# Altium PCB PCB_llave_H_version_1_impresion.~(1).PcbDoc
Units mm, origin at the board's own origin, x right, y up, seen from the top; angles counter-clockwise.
Board outline 85.85 x 71.63 mm, 2 copper layers (Top Layer, Bottom Layer); 58 components, 33 nets, 172 pads, 5 vias.
Unrouted connection lines stored in the file: 5.
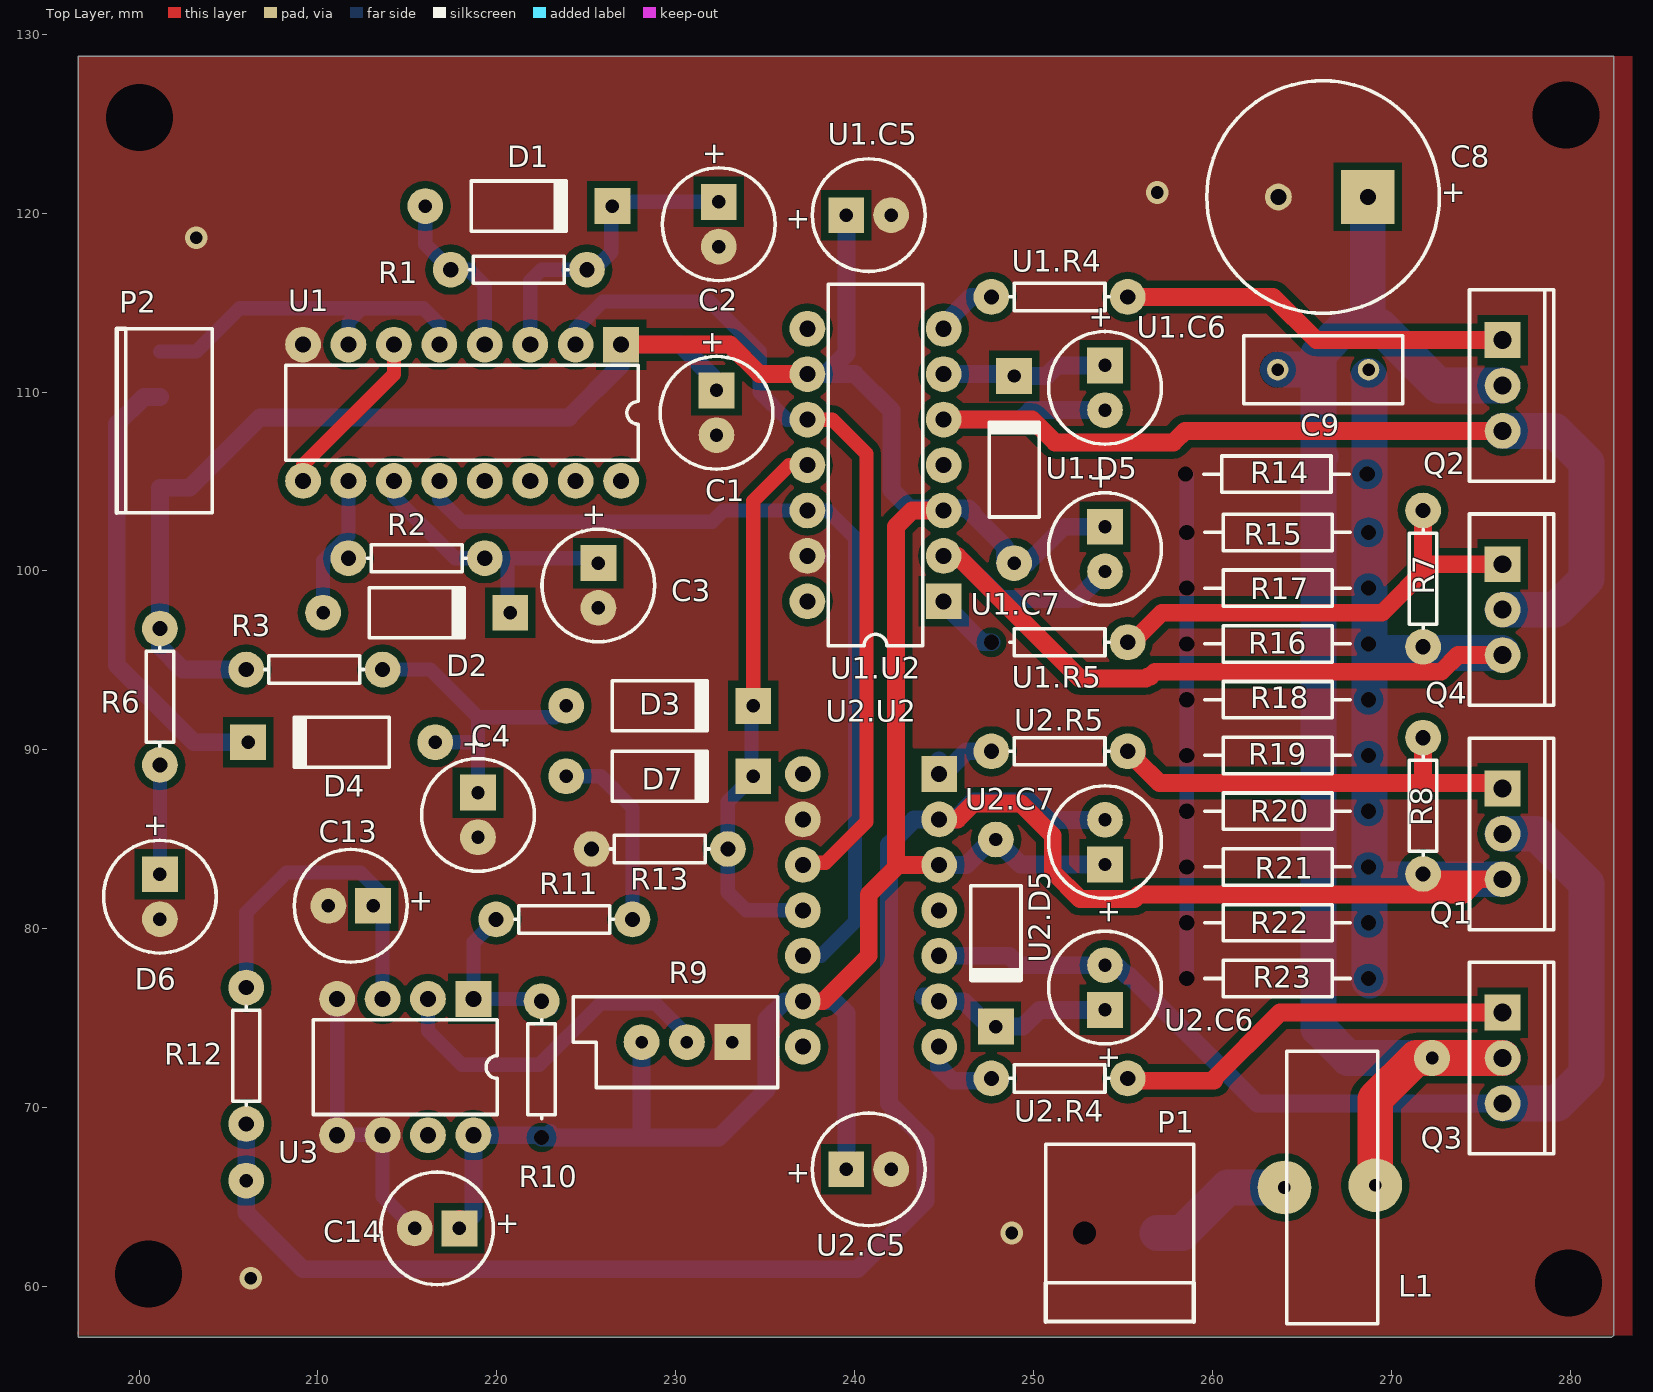
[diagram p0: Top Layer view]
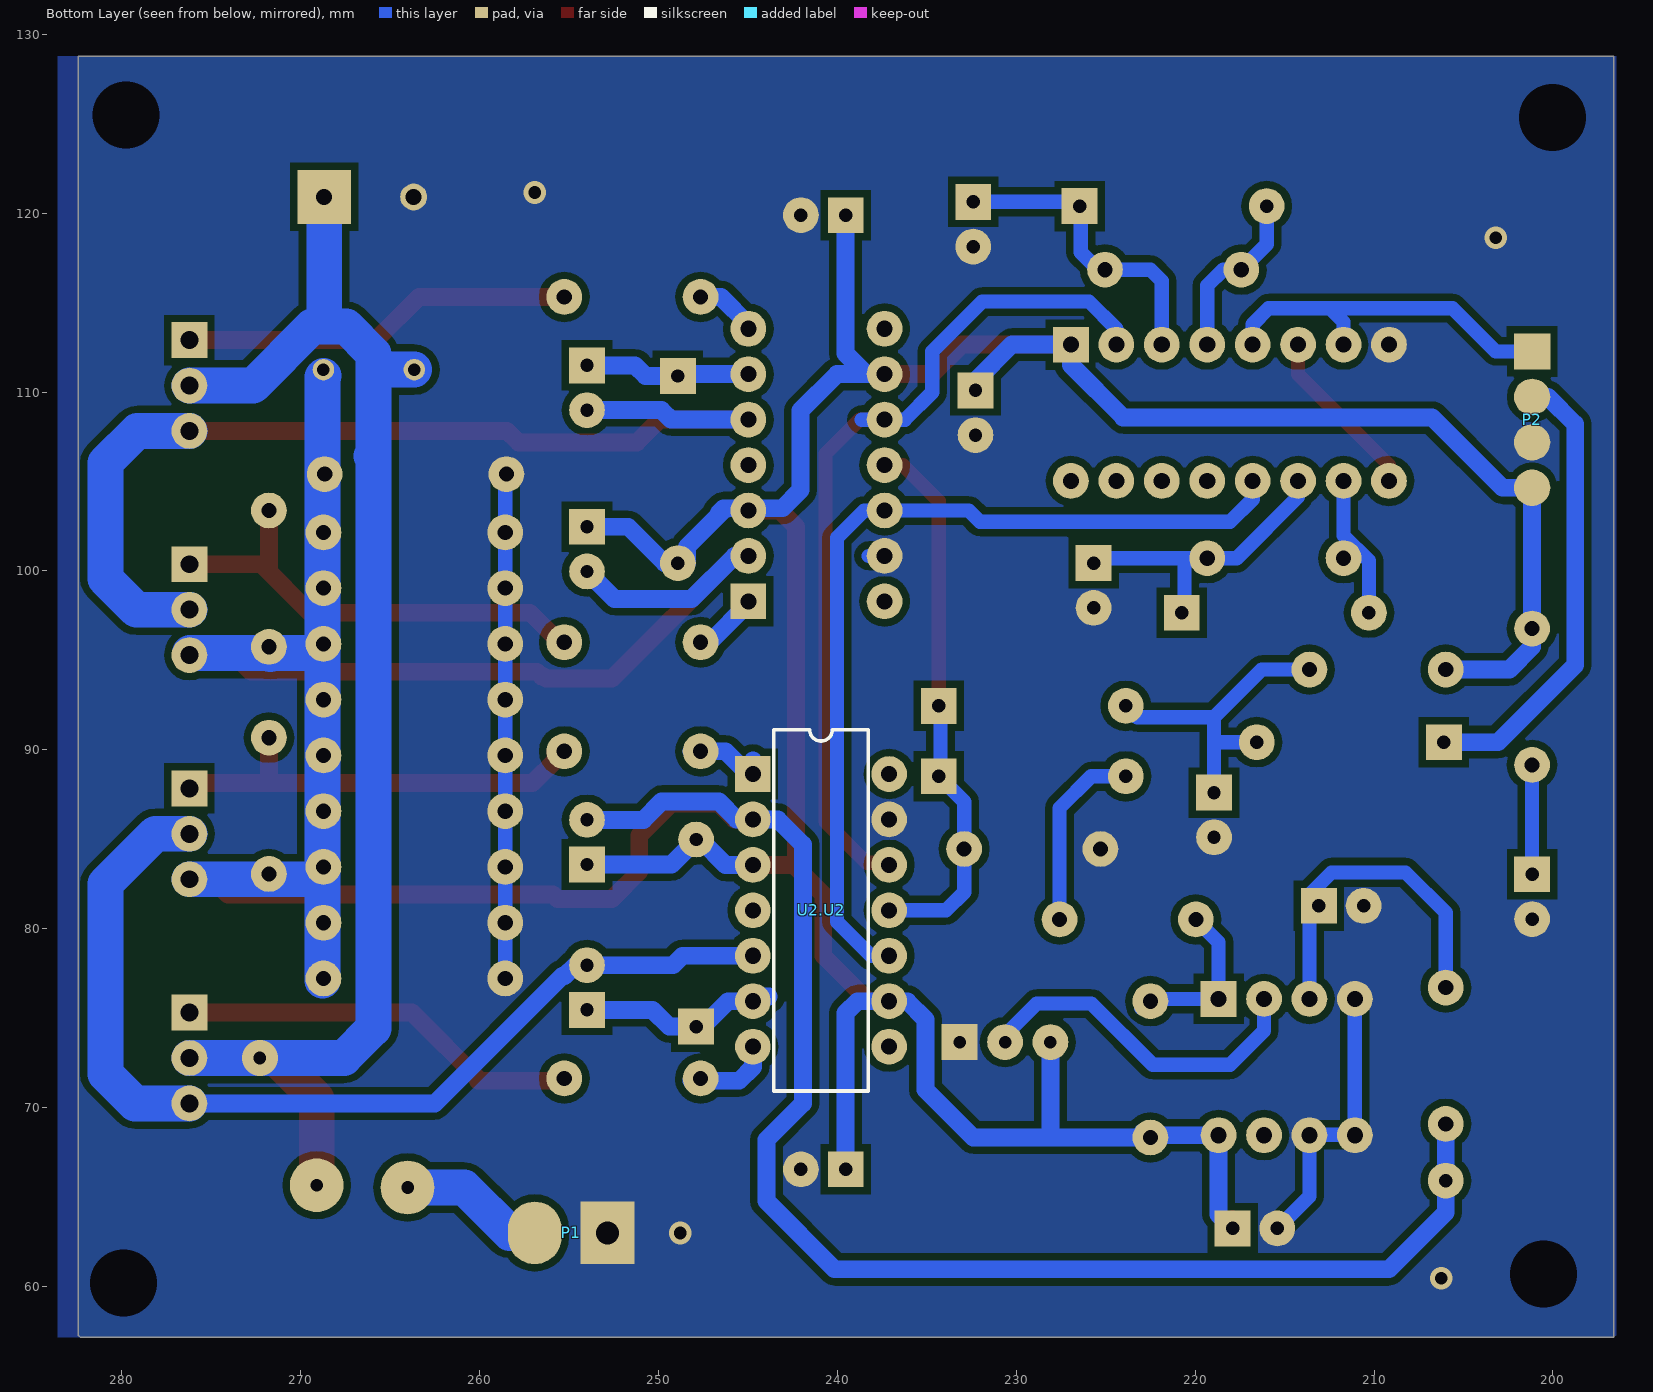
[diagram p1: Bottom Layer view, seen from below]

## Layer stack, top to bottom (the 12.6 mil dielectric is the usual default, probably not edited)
Top Layer: signal copper 0.0356
Dielectric: dielectric 0.32, FR-4, Dk 4.8
Bottom Layer: signal copper 0.0356

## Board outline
196.596,128.778 282.448,128.778 282.448,57.277 282.321,57.15 196.596,57.15

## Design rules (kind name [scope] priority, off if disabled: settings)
Clearance [All] p1: gap=0.4
ComponentClearance [All] p1: gap=0.254 collisioncheckmode=2 verticalgap=0.254
PlaneConnect [All] p1: planeconnectstyle=Direct reliefexpansion=0.508 reliefentries=4 reliefconductorwidth=0.254 reliefairgap=0.254
PolygonConnect [All] p1: connectstyle=Direct reliefconductorwidth=0.254 reliefentries=4 polygonreliefangle="90 Angle"
RoomDefinition U2 [InComponentClass('U2')] p1: confinementstyle=ConfineIn formatcopy=TRUE lockcomponents=FALSE outline 276.86,69.977 229.235,69.977 229.235,101.854 276.86,101.854
RoomDefinition U1 [InComponentClass('U1')] p2: confinementstyle=ConfineIn formatcopy=TRUE lockcomponents=FALSE outline 271.272,125.984 230.759,125.984 230.759,94.361 271.272,94.361
RoomDefinition U_Puente_H [InComponentClass('U_Puente_H')] p3: confinementstyle=ConfineIn formatcopy=TRUE lockcomponents=FALSE outline 282.448,127.635 282.448,57.277 247.65,57.277 247.65,127.635
RoomDefinition U_INITShutdown [InComponentClass('U_INITShutdown')] p4: confinementstyle=ConfineIn formatcopy=TRUE lockcomponents=FALSE outline 198.501,98.425 198.501,82.677 236.347,82.677 236.347,98.425
RoomDefinition U_Shutdown [InComponentClass('U_Shutdown')] p5: confinementstyle=ConfineOut formatcopy=TRUE lockcomponents=FALSE outline 201.041,96.266 202.438,96.266 202.438,92.964 201.041,92.964
RoomDefinition Llave_H_esquema [InComponentClass('Llave_H_esquema')] p6: confinementstyle=ConfineIn formatcopy=TRUE lockcomponents=FALSE outline 196.596,57.277 282.448,57.277 282.448,128.778 196.596,128.778
RoomDefinition U_4049 [InComponentClass('U_4049')] p7: confinementstyle=ConfineIn formatcopy=TRUE lockcomponents=FALSE outline 206.375,93.853 240.411,93.853 240.411,124.333 206.375,124.333
RoutingVias [All] p1: holewidth=0.711 width=1.27 viastyle="Through Hole" minholewidth=0.711 minwidth=1.27 maxholewidth=0.711 maxwidth=1.27
SolderMaskExpansion [All] p1: expansion=0.102
TestPointUsage [All] p1: valid=0 allowmultiple=FALSE
Testpoint [All] p1: side=15 testpointundercomponent=TRUE minsize=1.016 maxsize=2.54 preferedsize=1.524 minholesize=0 maxholesize=1.016 preferedholesize=0.813 testpointgrid=0.025 style=1023 order=0-112345678
Width [All] p1: maxlimit=3 minlimit=0.8 preferedwidth=1
17 further rules are at their usual default settings.

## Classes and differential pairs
component class U2: D5 U2.C5 U2.C6 U2.C7 U2.D5 U2.R4 U2.R5 U2.U2 U_2.D5 U_2_C5 U_2_C6 U_2_C7 U_2_R4 U_2_R5 U_2_U2
component class U1: U1.C5 U1.C6 U1.C7 U1.D5 U1.R4 U1.R5 U1.U2 U_1_C5 U_1_C6 U_1_C7 U_1_D5 U_1_R4 U_1_R5 U_1_U2
component class U_INITShutdown: C4 D3 D4 R3
channel class IR2110: U1 U2
component class U_Shutdown: C13 C14 D7 R9 R10 R11 R12 R13 R14 R15 R16 R17 R18 R19 R20 R21 R22 R23 U3
component class U_Puente_H: C8 C9 L1 Q1 Q2 Q3 Q4 R7 R8
component class U_4049: C1 C2 C3 D1 D2 R1 R2 U1
component class Llave_H_esquema: D6 P1 P2 R6

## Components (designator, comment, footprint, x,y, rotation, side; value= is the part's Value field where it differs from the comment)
C1 "Cap Pol1 0.1u" CAPPR2.5-6.3X5 232.283,108.839 r270 top
C2 "Cap Pol1" CAPPR2.5-6.3X5 232.41,119.38 r270 top
C3 "Cap Pol1" CAPPR2.5-6.3X5 225.679,99.187 r270 top
C4 "Cap Pol1 4.7u" CAPPR2.5-6.3X5 218.948,86.36 r270 top
C8 "Cap Pol1" CAPPR5-13X16 266.192,120.904 r180 top
C9 "Cap" RAD-0.2 266.192,111.252 r180 top
C13 "Cap Pol1 4.7u" CAPPR2.5-6.3X5 211.836,81.28 r180 top
C14 "Cap Pol1 0.1u" CAPPR2.5-6.3X5 216.662,63.246 r180 top
D1 "Diode1" DO-204AL 221.234,120.396 r0 top
D2 "Diode1" DO-204AL 215.519,97.663 r0 top
D3 "Diode1" DO-204AL 229.108,92.456 r0 top
D4 "Diode1" DO-204AL 211.328,90.424 r180 top
D6 "LED0" CAPPR2.5-6.3X5 201.168,81.788 r270 top
D7 "Diode1" DO-204AL 229.108,88.519 r0 top
L1 "Inductor" bobina_Choque 264.16,68.072 r270 top
P1 "Header 2" pwheader1x2 255.016,62.992 r0 top
P2 "Header 4" HDR1X5 193.548,104.648 r270 top
Q1 "IRF3205" TO-220AB 276.225,72.771 r270 top
Q2 "IRF3205" TO-220AB 276.225,110.363 r270 top
Q3 "IRF3205" TO-220AB 276.225,85.302 r270 top
Q4 "IRF3205" TO-220AB 276.225,97.832 r270 top
R1 "18k" AXIAL-0.3#1 221.234,116.84 r180 top
R2 "18k" AXIAL-0.3#1 215.519,100.711 r0 top
R3 "4.7k" AXIAL-0.3#1 209.804,94.488 r180 top
R6 "1.2k" AXIAL-0.3#1 201.168,92.964 r90 top
R7 "6.8" AXIAL-0.3#1 271.78,99.568 r90 top
R8 "6.8" AXIAL-0.3#2 271.78,86.868 r90 top
R9 "RPot" VR5 230.632,73.66 r180 top
R10 "3.3k" AXIAL-0.3#3 222.504,72.136 r270 top
R11 "470" AXIAL-0.3#1 223.774,80.518 r0 top
R12 "6.8" AXIAL-0.3#1 205.994,72.898 r90 top locked
R13 "10k" AXIAL-0.3#1 229.108,84.455 r0 top
R14 "Res2" AXIAL-0.4#1 263.585,105.41 r0 top
R15 "Res2" AXIAL-0.4#1 263.652,102.154 r0 top
R16 "Res2" AXIAL-0.4#1 263.652,99.037 r0 top
R17 "Res2" AXIAL-0.4#1 263.652,95.919 r0 top
R18 "Res2" AXIAL-0.4#1 263.652,92.802 r0 top
R19 "Res2" AXIAL-0.4#1 263.652,89.685 r0 top
R20 "Res2" AXIAL-0.4#2 263.652,86.568 r0 top
R21 "Res2" AXIAL-0.4#2 263.652,83.45 r0 top
R22 "Res2" AXIAL-0.4#2 263.652,80.333 r0 top
R23 "Res2" AXIAL-0.4#2 263.652,77.216 r0 top
U1 "MC54HC4049J" 620-09 218.059,108.839 r180 top
U1.C5 "Cap Pol1 4.7u" CAPPR2.5-6.3X5 240.792,119.888 r0 top (schematic designator C5)
U1.C6 "Cap Pol1" CAPPR2.5-6.3X5 254,110.236 r270 top (schematic designator C6)
U1.C7 "Cap Pol1" CAPPR2.5-6.3X5 254,101.219 r270 top (schematic designator C7)
U1.D5 "Diode" DO-204AL 248.92,105.664 r90 top (schematic designator D5)
U1.R4 "10" AXIAL-0.3#1 251.46,115.316 r0 top (schematic designator R4)
U1.R5 "10" AXIAL-0.3#4 251.46,96.012 r0 top (schematic designator R5)
U1.U2 "IR2110" PDIP14 241.173,105.918 r90 top (schematic designator U2)
U2.C5 "Cap Pol1 4.7u" CAPPR2.5-6.3X5 240.792,66.548 r0 top (schematic designator C5)
U2.C6 "Cap Pol1" CAPPR2.5-6.3X5 254,76.708 r90 top (schematic designator C6)
U2.C7 "Cap Pol1" CAPPR2.5-6.3X5 254,84.836 r90 top (schematic designator C7)
U2.D5 "Diode" DO-204AL 247.904,79.756 r270 top (schematic designator D5)
U2.R4 "10" AXIAL-0.3#1 251.46,71.628 r0 top (schematic designator R4)
U2.R5 "10" AXIAL-0.3#1 251.46,89.916 r0 top (schematic designator R5)
U2.U2 "IR2110" PDIP14 240.919,81.026 r270 bottom (schematic designator U2)
U3 "LM393N" 626-05 214.884,72.263 r180 top

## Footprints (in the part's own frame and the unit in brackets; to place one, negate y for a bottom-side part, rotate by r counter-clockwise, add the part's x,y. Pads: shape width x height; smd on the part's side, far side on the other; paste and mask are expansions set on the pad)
620-09 [mm] "DIP; 16 Leads; Row Spacing 7.62 mm; Pitch 2.54 mm"
  rect 2x2 hole 0.9: 1(-8.89,-3.81)
  round 2 hole 0.9: 2(-6.35,-3.81) 3(-3.81,-3.81) 4(-1.27,-3.81) 5(1.27,-3.81) 6(3.81,-3.81) 7(6.35,-3.81) 8(8.89,-3.81) 9(8.89,3.81) 10(6.35,3.81) 11(3.81,3.81) 12(1.27,3.81) 13(-1.27,3.81) 14(-3.81,3.81) 15(-6.35,3.81) 16(-8.89,3.81)
  silkscreen extent -9.85,-2.65 9.85,2.65
626-05 [mm] "DIP; 8 Leads; Row Spacing 7.62 mm; Pitch 2.54 mm"
  rect 2x2 hole 0.9: 1(-3.81,-3.81)
  round 2 hole 0.9: 2(-1.27,-3.81) 3(1.27,-3.81) 4(3.81,-3.81) 5(3.81,3.81) 6(1.27,3.81) 7(-1.27,3.81) 8(-3.81,3.81)
  silkscreen extent -5.15,-2.65 5.15,2.65
AXIAL-0.3#1 [mm] "Resistor; 2 Leads"
  round 2 hole 0.85: 1(-3.81,0) 2(3.81,0)
  silkscreen extent -2.77,-0.76 2.77,0.76
AXIAL-0.3#2 [mm] "Resistor; 2 Leads"
  round 2 hole 0.85 paste+0 mask+0.102: 1(-3.81,0)
  round 2 hole 0.85: 2(3.81,0)
  silkscreen extent -2.77,-0.76 2.77,0.76
AXIAL-0.3#3 [mm] "Resistor; 2 Leads"
  round 2 hole 0.85: 1(-3.81,0)
  round 0 / inner round 0 / far side round 2 hole 0.85: 2(3.81,0)
  silkscreen extent -2.77,-0.76 2.77,0.76
AXIAL-0.3#4 [mm] "Resistor; 2 Leads"
  round 0 / inner round 0 / far side round 2 hole 0.85: 1(-3.81,0)
  round 2 hole 0.85: 2(3.81,0)
  silkscreen extent -2.77,-0.76 2.77,0.76
AXIAL-0.4#1 [mm] "Resistor; 2 Leads"
  round 0 / inner round 0 / far side round 2 hole 0.85: 1(-5.08,0) 2(5.08,0)
  silkscreen extent -4.06,-1.02 4.06,1.02
AXIAL-0.4#2 [mm] "Resistor; 2 Leads"
  round 0 / inner round 0 / far side round 2 hole 0.85: 1(-5.08,0)
  round 0 / inner round 0 / far side round 2 hole 0.85 unplated: 2(5.08,0)
  silkscreen extent -4.06,-1.02 4.06,1.02
bobina_Choque [mm]
  round 3 hole 0.7: 1(2.54,-0.127) 2(2.413,4.953)
  silkscreen extent -5.08,0 10.16,5.08
CAPPR2.5-6.3X5 [mm] "Capacitor, Electrolytic, Radial; Body 6.3 x 5 mm (Dia.xH typ); Pin Spacing 2.5 mm (typ)"
  rect 2x2 hole 0.75: 1(-1.25,0)
  round 2 hole 0.75: 2(1.25,0)
  silkscreen extent -3.15,-3.15 3.15,3.15
CAPPR5-13X16 [mm] "Capacitor, Electrolytic, Radial; Body 13 x 16 mm (Dia.xH typ); Pin Spacing 5 mm (typ)"
  rect 3x3 hole 0.9: 1(-2.5,0)
  round 1.5 hole 0.9: 2(2.5,0)
  silkscreen extent -6.5,-6.5 6.5,6.5
DO-204AL [mm] "Diode, Axial; Body 5.2 x 2.7 mm (LxDia. max), Lead Dia. 0.86 mm (max)"
  round 2 hole 0.75: 1(-5.23,0)
  rect 2x2 hole 0.75: 2(5.23,0)
  silkscreen extent -2.65,-1.4 2.75,1.4
HDR1X5 [mil]
  rect 80x80 smd far side: 1(-300,300)
  round 80 smd far side: 2(-200,300) 3(-100,300) 4(0,300)
  silkscreen extent -350,205 55,415
PDIP14 [mm] "DIP; 14 Leads; Row Spacing 7.62 mm; Pitch 2.54 mm"
  rect 2x2 hole 0.9: 1(-7.62,-3.81)
  round 2 hole 0.9: 2(-5.08,-3.81) 3(-2.54,-3.81) 4(0,-3.81) 5(2.54,-3.81) 6(5.08,-3.81) 7(7.62,-3.81) 8(7.62,3.81) 9(5.08,3.81) 10(2.54,3.81) 11(0,3.81) 12(-2.54,3.81) 13(-5.08,3.81) 14(-7.62,3.81)
  silkscreen extent -10.1,-2.65 10.1,2.65
pwheader1x2 [mm]
  round 0 / inner round 0 / far side rect 3x3.5 hole 1.3: 1(-2.159,0)
  oval 3x3.5 smd far side: 2(1.905,0)
  silkscreen extent -4.32,-4.95 3.94,4.95
RAD-0.2 [mm] "Jumper Wire; 2 Leads"
  round 1.2 hole 0.7: 1(-2.54,0) 2(2.54,0)
  silkscreen extent -4.44,-1.91 4.44,1.91
TO-220AB [mm] "TO, Thru-Hole, Vertical, Heatsink Mounted; 3 In-Line Leads; Pitch 2.54 mm"
  rect 2x2 hole 1: 1(-2.54,0)
  round 2 hole 1: 2(0,0) 3(2.54,0)
  silkscreen extent -5.35,-1.85 5.35,2.85
VR5 [mm] "Potentiometer; 3 Leads"
  rect 2x2 hole 0.7: 1(-2.54,0)
  round 2 hole 0.7: 2(2.54,0) 3(0,0)
  silkscreen extent -5.08,-2.54 6.35,2.54

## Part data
C1 C4 C14 U1.C5 U2.C5: library part "Cap Pol1", "Polarized Capacitor (Radial)"
C2 C3 C8 U1.C6 U1.C7 U2.C6 U2.C7: "Polarized Capacitor (Radial)"
C9: "Capacitor"
C13: library part "Cap Pol1", "Polarized 16V"
D1 D2: library part Diode, "1N4148"
D3 D4 D7: library part Diode, "1n4148"
D6: "Typical INFRARED GaAs LED"
P1: "Header, 2-Pin"
P2: "Header, 4-Pin"
Q1 Q2 Q3 Q4: "HEXFET Power MOSFET"
R1 R2 R3 R6 R7 R8 U1.R4 U1.R5 U2.R4 U2.R5: library part Res2, "Resistor"
R9: "Potenciomentro multivuelta"
R10 R11 R12 R13: library part Res2, "metal film 1/2 W"
R14 R15 R16 R17 R18 R19 R20 R21 R22 R23: "metal film 1W"
U1: "Hex Inverting Buffer/Logic-Level Down Converter"
U1.D5 U2.D5: "1N5819"
U1.U2 U2.U2: "High and Low Side Driver"
U3: "Dual Comparator"

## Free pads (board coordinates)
  round 1.524 hole 3.75: 0(200.025,125.349) 0(200.533,60.706) 0(279.781,125.476) 0(279.908,60.198)
  round 2 hole 0.762: 1(205.994,65.913)

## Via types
v1: diameter 1.27, hole 0.711, Top Layer to Bottom Layer, 4 vias
v2: diameter 2, hole 0.711, Top Layer to Bottom Layer, 1 vias

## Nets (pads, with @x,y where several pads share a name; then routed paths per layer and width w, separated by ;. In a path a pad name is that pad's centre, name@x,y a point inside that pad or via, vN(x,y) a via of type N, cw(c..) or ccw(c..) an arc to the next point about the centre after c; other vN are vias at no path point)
COMMON: C9.1 pad.1 Q3.3 Q4.3 R7.1 R8.1 R12.1 R14.2 R15.2 R16.2 R17.2 R18.2 R19.2 R20.2 R21.2 R22.2 R23.2 U1.C7.2 U1.U2.2 U2.C7.2 U2.U2.2 | length 217.5
  Top Layer w1: U2.U2.2 245.745,86.106 246.634,86.995 249.301,86.995 251.079,85.217 251.079,83.185 252.603,81.661 255.646,81.661 255.9,81.915 274.066,81.915 274.913,82.762 ; U1.U2.2 245.745,100.838 252.603,93.98 256.286,93.98 256.413,94.107 256.54,94.107 256.794,94.361 272.796,94.361 273.727,95.292 Q4.3 ; R8.1@271.78,82.762 Q3.3
  Bottom Layer w1: R12.1 205.994,64.135 209.169,60.96 240.157,60.96 243.967,64.77 243.967,68.199 241.935,70.231 241.935,84.709 243.332,86.106 245.633,86.106 246.629,87.102 249.829,87.102 250.845,86.086 U2.C7.2 ; U1.U2.2 245.745,100.838 248.158,98.425 252.456,98.425 U1.C7.2 ; R7.1@271.713,95.377 271.798,95.292 Q4.3
  Bottom Layer w2: C9.1@268.732,110.906 268.792,110.845 R23.2@268.792,77.089 ; R21.2@268.792,82.762 Q3.3 ; R17.2@268.792,95.411 Q4.3@276.191,95.411 ; R7.1@271.713,95.345 R7.1@271.78,95.411
GND: C1.2 C2.2 C3.2 C4.2 C8.2 C13.2 C14.2 D6.2 P1.1 P2.3 pad.0 R9.1 R13.1 R14.1 R15.1 R16.1 R17.1 R18.1 R19.1 R20.1 R21.1 R22.1 R23.1 U1.8 U1.C5.2 U1.U2.13 U2.C5.2 U2.U2.13 U3.4 U3.5 U3.6 | length 45.2
  Top Layer w0.8: U3.5 211.094,68.473 U3.5@211.074,68.493 ; U3.6@213.594,68.473 U3.6
  Bottom Layer w0.8: U3.5 U3.4 ; U3.5@211.094,68.473 U3.6@213.594,68.473 ; U3.6 213.614,65.044 C14.2 ; U1.U2.13 U1.U2.13@238.252,100.838 ; R23.1 R14.1@258.572,105.343
  other v1: 206.248,60.452 248.793,62.992 203.2,118.618 256.921,121.158
HO1: Q2.1 U1.R4.2 | length 22
  Top Layer w1: U1.R4.2 263.398,115.316 265.811,112.903 Q2.1
HO2: Q1.1 U2.R4.2 | length 22
  Top Layer w1: U2.R4.2@255.905,71.501 260.096,71.501 ; 259.969,71.501 263.779,75.311 Q1.1
IN_SD: D4.2 P2.2 | length 25.6
  Bottom Layer w1: P2.2 200.279,109.728 198.755,108.204 198.755,94.742 203.073,90.424 D4.2
LO1: Q4.1 R7.2 U1.R5.2 | length 26.4
  Top Layer w1: U1.R5.2 255.524,96.012 257.175,97.663 269.494,97.663 272.203,100.372 Q4.1 ; R7.2@271.78,103.632 271.78,99.972 271.791,99.96
LO2: Q3.1 R8.2 U2.R5.2 | length 24.5
  Top Layer w1: U2.R5.2@255.778,89.916 255.778,89.408 257.048,88.138 275.929,88.138 Q3.1 ; R8.2@271.526,91.059 R8.2@271.78,90.805 ; 271.78,88.138 R8.2
MOTOR+: Q2.3 Q4.2 U1.C6.2 U1.U2.5 | length 58.6
  Top Layer w1: U1.U2.5 249.936,108.458 251.206,107.188 257.836,107.188 258.471,107.823 Q2.3
  Bottom Layer w1: U1.U2.5 249.301,108.458 249.829,108.986 U1.C6.2
  Bottom Layer w2: Q4.2 279.188,97.832 280.924,99.568 280.924,106.045 279.146,107.823 Q2.3
MOTOR-: Q1.3 Q3.2 U2.C6.2 U2.U2.5 | length 56.8
  Bottom Layer w1: U2.U2.5 248.666,78.486 249.194,77.958 254.655,77.958 255.255,77.358 255.382,77.358 262.509,70.231 Q1.3
  Bottom Layer w2: Q1.3 279.273,70.231 280.924,71.882 280.924,82.508 278.13,85.302 Q3.2
NetC2_1: C2.1 D1.2 R1.1 U1.3 | length 17.4
  Bottom Layer w0.8: U1.3 221.869,116.205 222.504,116.84 225.425,116.84 226.403,117.818 226.403,120.335 226.698,120.63 C2.1
NetC3_1: C3.1 D2.2 R2.2 U1.11 | length 17
  Bottom Layer w0.8: U1.11 214.249,104.14 217.678,100.711 225.405,100.711 C3.1 ; 220.599,100.711 220.599,97.813 D2.2
NetC4_1: C4.1 D3.1 D4.1 R3.1 | length 18.2
  Bottom Layer w0.8: R3.1 216.281,94.488 218.948,91.821 ; D4.1 218.948,90.424 ; C4.1 218.948,91.821 ; D3.1 223.243,91.821 218.948,91.821
NetC13_1: C13.1 R12.2 U3.3 | length 19.1
  Bottom Layer w0.8: R12.2 205.994,80.899 208.24,83.145 212.384,83.145 213.614,81.915 U3.3
NetD1_1: D1.1 R1.2 U1.4 | length 9.7
  Bottom Layer w0.8: D1.1 216.004,118.26 R1.2 218.44,116.84 219.329,115.951 U1.4
NetD2_1: D2.1 R2.1 U1.10 | length 8
  Bottom Layer w0.8: D2.1 210.289,100.561 211.709,101.981 U1.10
NetD6_1: D6.1 R6.1 | length 6.1
  Bottom Layer w0.8: D6.1 R6.1
NetD7_1: D7.1 R11.2 | length 10.7
  Bottom Layer w0.8: D7.1 225.806,88.519 227.584,86.741 R11.2
NetR9_3: R9.3 U3.2 | length 19.6
  Bottom Layer w0.8: U3.2 216.154,74.295 218.059,72.39 222.377,72.39 225.806,75.819 228.854,75.819 230.632,74.041 R9.3
NetR10_1: R10.1 R11.1 U3.1 | length 9.5
  Bottom Layer w0.8: R11.1 218.694,79.248 U3.1 222.504,76.073 R10.1@223.012,75.565
NetU1.C6_1: U1.C6.1 U1.D5.2 U1.U2.6 | length 9.8
  Bottom Layer w1: U1.U2.6 248.308,110.998 248.412,110.894 250.721,110.894 251.313,111.486 U1.C6.1 ; U1.D5.2@248.943,111.252 U1.D5.2@249.301,110.894
NetU1.R4_1: U1.R4.1 U1.U2.7 | length 3.8
  Bottom Layer w1: U1.U2.7 244.983,113.792 246.507,115.316 U1.R4.1@247.904,115.316
NetU1.R5_1: U1.R5.1 U1.U2.1 | length 3.7
  Bottom Layer w1: U1.U2.1 244.983,98.171 247.142,96.012 U1.R5.1
NetU1_6: U1.6 U1.9 | length 9.9
  Top Layer w0.8: U1.9 209.169,105.918 214.249,110.998 U1.6
  Bottom Layer w0.8: U1.9 U1.9@209.169,105.156
NetU2.C6_1: U2.C6.1 U2.D5.2 U2.U2.6 | length 10.8
  Bottom Layer w1: U2.U2.6@243.84,76.2 U2.U2.6@244.602,76.2 ; U2.U2.6 246.126,75.946 U2.D5.2@247.673,74.399 ; U2.D5.2 249.405,74.526 250.337,75.458 U2.C6.1
NetU2.R4_1: U2.R4.1 U2.U2.7 | length 4.9
  Bottom Layer w1: U2.U2.7 244.729,72.263 245.491,71.501 U2.R4.1@248.158,71.501
NetU2.R5_1: U2.R5.1 U2.U2.1 | length 4.7
  Bottom Layer w1: U2.U2.1@244.729,89.408 U2.U2.1 244.983,88.646 246.253,89.916 U2.R5.1@248.158,89.916
PWM: P2.1 U1.5 U1.7 | length 20.5
  Bottom Layer w0.8: P2.1 203.2,112.268 205.613,114.681 215.9,114.681 216.789,113.792 U1.5 ; U1.7 211.709,113.919 212.471,114.681
SD: D3.2 D7.2 R13.2 U1.U2.11 U2.U2.11 | length 31.1
  Top Layer w0.8: D3.2 234.338,103.909 236.347,105.918 U1.U2.11
  Bottom Layer w0.8: D7.2@234.241,88.422 234.241,92.359 D3.2 ; D7.2 232.918,87.099 232.918,82.042 233.934,81.026 U2.U2.11
U1.HIN: U1.2 U1.U2.10 U2.U2.12 | length 48.9
  Top Layer w0.8: U2.U2.12@237.236,83.693 238.379,83.693 240.665,85.979 240.665,106.553 238.76,108.458 U1.U2.10
  Bottom Layer w0.8: U1.2 224.409,113.538 225.933,115.062 231.902,115.062 234.696,112.268 234.696,109.982 236.22,108.458 238.633,108.458
U1.LIN: U1.12 U1.U2.12 U2.U2.10 | length 50.9
  Bottom Layer w0.8: U1.12 216.789,104.013 218.059,102.743 232.029,102.743 232.664,103.378 238.506,103.378 240.03,101.854 240.03,80.391 238.125,78.486 U2.U2.10
VCC_MOTOR: L1.1 P1.2 | length 8.2
  Bottom Layer w2: P1.2 258.318,62.992 260.858,65.532 L1.1
VCC_MOTOR_FILTRADO: C8.1 C9.2 L1.2 Q1.2 Q2.2 | length 83.3
  Top Layer w2: L1.2 269.113,70.485 271.399,72.771 Q1.2
  Bottom Layer w2: C9.2 265.811,111.252 265.938,111.125 ; 265.938,106.299 266.065,106.426 ; 268.692,113.959 C8.1 ; Q1.2 267.589,72.771 265.938,74.422 265.938,112.141 267.462,113.665 269.367,113.665 272.669,110.363 Q2.2
  other v2: 272.288,72.771
VDD: C1.1 C14.1 P2.4 R3.2 R6.2 R9.2 R10.2 U1.1 U1.C5.1 U1.C7.1 U1.D5.1 U1.U2.3 U1.U2.9 U2.C5.1 U2.C7.1 U2.D5.1 U2.U2.3 U2.U2.9 U3.8 | length 188.7
  Top Layer w0.8: C14.1 C14.1@217.912,63.861 ; U3.8@218.567,68.707 218.694,68.58 U3.8
  Top Layer w1: U1.1 233.045,112.649 234.696,110.998 U1.U2.9 ; U2.U2.9 238.252,75.946 240.792,78.486 240.792,81.915 242.443,83.566 U2.U2.3 ; 242.316,83.439 242.316,102.489 243.205,103.378 U1.U2.3
  Bottom Layer w0.8: R10.2@222.994,68.689 R10.2@223.012,68.672 ; C1.1 C1.1@232.283,110.49
  Bottom Layer w1: R3.2 202.438,94.488 201.168,95.758 P2.4 202.819,104.648 206.756,108.585 224.028,108.585 226.949,111.506 U1.1 230.251,112.649 232.283,110.617 C1.1 ; C14.1 218.694,64.028 U3.8 R10.2@222.758,68.453 ; R10.2 232.41,68.326 235.077,70.993 235.077,74.93 236.093,75.946 238.887,75.946 239.542,75.291 U2.C5.1 ; 228.092,68.326 R9.2 ; U1.U2.9 240.03,110.998 242.062,108.966 242.062,104.521 243.078,103.505 246.38,103.505 246.634,103.251 ; 238.379,110.998 239.542,112.161 U1.C5.1 ; U2.U2.3 246.253,83.566 U2.D5.1@247.546,84.859 ; 246.38,103.378 248.412,101.346 U1.D5.1@248.412,100.434 ; U2.D5.1 247.904,84.963 249.281,83.586 U2.C7.1 ; U1.D5.1 249.659,100.434 251.694,102.469 U1.C7.1
pads on no net: U1.13 U1.14 U1.15 U1.16 U1.U2.4 U1.U2.8 U1.U2.14 U2.U2.4 U2.U2.8 U2.U2.14 U3.7

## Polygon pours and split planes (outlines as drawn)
GND on Top Layer "Top Layer-GND" (solid, remove dead copper, pour order 1000): 196.598,128.778 283.464,128.778 283.464,57.277 196.598,57.277 196.469,57.404 196.598,57.531
GND on Bottom Layer "Bottom Layer-GND" (solid, remove dead copper, pour order 1001): 196.469,128.778 283.591,128.778 283.591,57.15 196.597,57.15 196.469,57.277

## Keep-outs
Keep-Out Layer:
  lines w0.254: 191.008,218.567 191.262,218.313 191.262,52.451 317.373,52.451 317.246,52.578 317.246,218.44 317.119,218.567 191.008,218.567

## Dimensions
258.064,52.578 to 207.391,218.567 on Top Layer
191.008,215.519 to 316.992,211.201 on Top Layer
